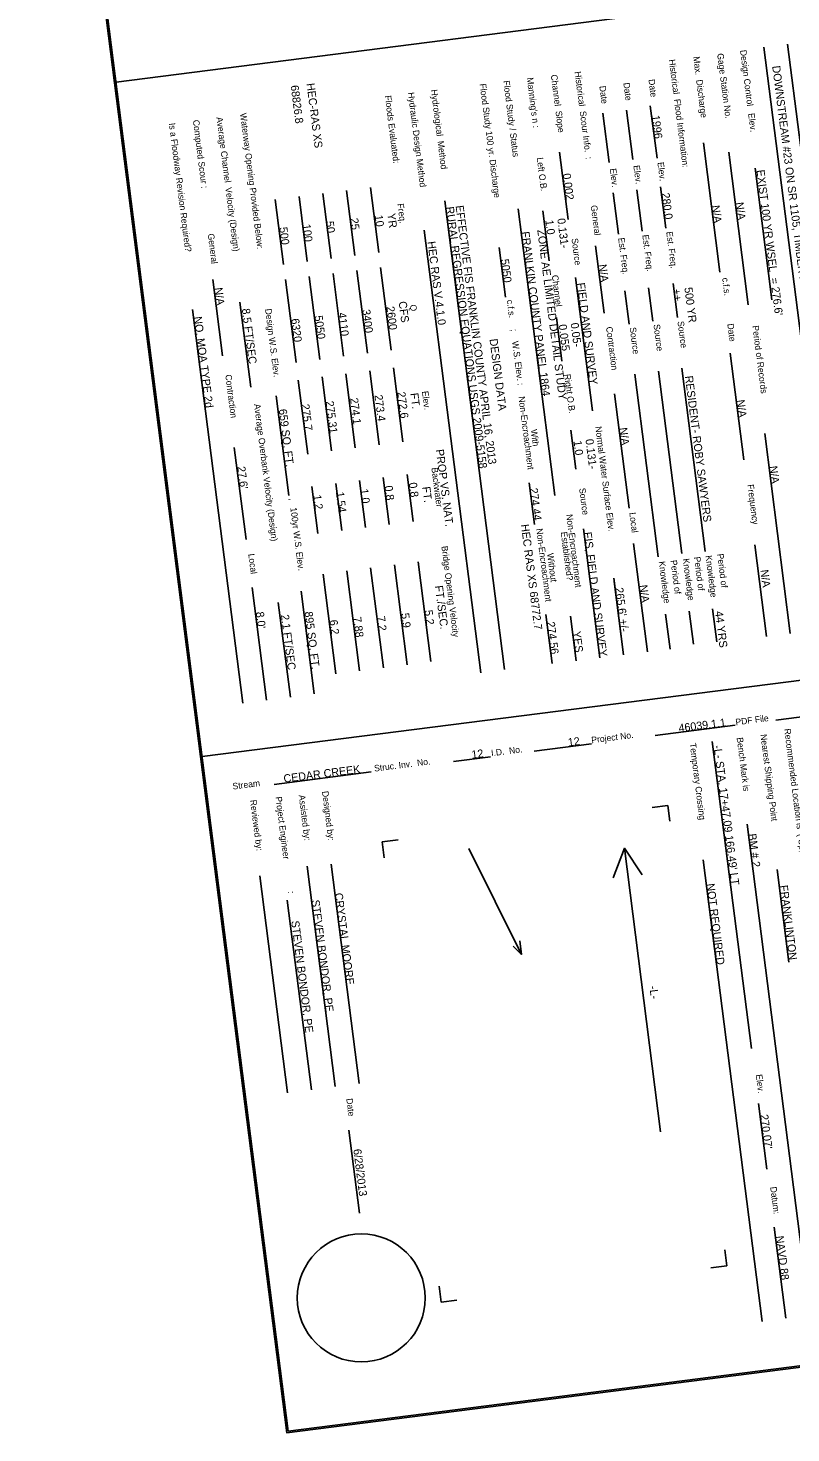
# Model space of a CAD drawing. Extents: x 2166991 to 2168413, y 842679 to 844296.
# Drawn here: x 2166991 to 2167468, y 842679 to 843557 of the extents above; entities that cross this region are included whole.
import ezdxf

# ---------------------------------------------------------------- set-up
doc = ezdxf.new("R2010")
doc.units = 0
for name, color, linetype in [('Old_Level_19', 7, 'Continuous'), ('Prop Plan Preparation Cover Label', 7, 'Continuous'), ('Prop Plan Preparation Sheet Bridge Report Limited Study CELL', 7, 'Continuous'), ('Sheet Plot Border Outside CELL', 7, 'Continuous')]:
    doc.layers.add(name, color=color, linetype=linetype)

msp = doc.modelspace()

# ---------------------------------------------------------------- linework, layer by layer
at = {"layer": 'Old_Level_19'}
for p, q in [((2167364.14, 843044.08), (2167357.17, 843025.57)), ((2167299.79, 842977.75), (2167294.54, 842982.82))]:
    msp.add_line(p, q, dxfattribs=at)
for points in [[(2167266.81, 843043.83), (2167299.79, 842977.75), (2167298.7, 842986.29)], [(2167386.79, 842866.75), (2167364.14, 843044.08), (2167375.24, 843027.53)]]:
    msp.add_lwpolyline(points, dxfattribs=at)
at = {"layer": 'Prop Plan Preparation Sheet Bridge Report Limited Study CELL'}
for p, q in [((2167046.37, 843522.95), (2167591.94, 843592.64)), ((2167497.56, 843182.31), (2167451.28, 843544.69)), ((2167512.44, 843184.21), (2167466.16, 843546.59)), ((2167380.33, 843508.19), (2167384.53, 843475.3)), ((2167350.63, 843503.57), (2167354.58, 843472.75)), ((2167365.51, 843505.47), (2167369.44, 843474.64)), ((2167423.86, 843404.17), (2167413.54, 843484.99)), ((2167328.93, 843437.01), (2167323.56, 843479.07)), ((2167441.6, 843383.67), (2167429.4, 843479.19)), ((2167456.32, 843386.86), (2167445.81, 843469.08)), ((2167195.7, 843414.6), (2167190.52, 843455.16)), ((2167210.58, 843416.5), (2167205.4, 843457.06)), ((2167371.93, 843455.61), (2167375.23, 843429.7)), ((2167386.8, 843457.51), (2167390.11, 843431.6)), ((2167151.06, 843408.9), (2167145.88, 843449.45)), ((2167165.94, 843410.8), (2167160.76, 843451.35)), ((2167180.82, 843412.7), (2167175.64, 843453.25)), ((2167289.26, 843155.7), (2167251.84, 843448.63)), ((2167357.05, 843453.71), (2167360.35, 843427.8)), ((2167320.71, 843264.62), (2167297.83, 843443.75)), ((2167317.12, 843411.12), (2167313.11, 843442.49)), ((2167274.38, 843153.8), (2167239.04, 843430.48)), ((2167289.77, 843388.48), (2167285.81, 843419.45)), ((2167351.53, 843378.49), (2167346.16, 843420.55)), ((2167173.75, 843349.64), (2167167.14, 843401.42)), ((2167188.63, 843351.54), (2167182.02, 843403.32)), ((2167203.51, 843353.44), (2167196.9, 843405.22)), ((2167218.39, 843355.34), (2167211.78, 843407.12)), ((2167113, 843351.76), (2167106.88, 843399.61)), ((2167158.87, 843347.74), (2167152.26, 843399.52)), ((2167344.2, 843317.53), (2167333.57, 843400.7)), ((2167367.07, 843371.56), (2167364.4, 843392.48)), ((2167381.95, 843373.46), (2167379.28, 843394.38)), ((2167397.25, 843375.73), (2167394.54, 843396.96)), ((2167130.6, 843332.3), (2167123.83, 843385.32)), ((2167125.59, 843134.8), (2167094.16, 843380.82)), ((2167325.11, 843348.56), (2167321.64, 843375.74)), ((2167438.86, 843286.78), (2167430.34, 843353.46)), ((2167195.95, 843294.27), (2167190.04, 843340.53)), ((2167210.83, 843296.17), (2167204.92, 843342.43)), ((2167225.71, 843298.07), (2167219.8, 843344.33)), ((2167370.65, 843340.3), (2167385.21, 843226.32)), ((2167385.53, 843342.2), (2167400.09, 843228.22)), ((2167400.04, 843344.06), (2167414.65, 843229.65)), ((2167166.19, 843290.47), (2167160.28, 843336.73)), ((2167181.07, 843292.37), (2167175.16, 843338.63)), ((2167154.38, 843264.5), (2167146.42, 843326.82)), ((2167367.1, 843256.58), (2167357.96, 843328.15)), ((2167333.75, 843280.92), (2167330.63, 843305.37)), ((2167467.83, 843178.32), (2167451.86, 843303.37)), ((2167127.64, 843237.11), (2167120.29, 843294.61)), ((2167172.54, 843240.74), (2167168.79, 843270.09)), ((2167187.42, 843242.64), (2167183.67, 843271.99)), ((2167202.3, 843244.54), (2167198.55, 843273.89)), ((2167217.18, 843246.44), (2167213.43, 843275.79)), ((2167232.06, 843248.34), (2167228.31, 843277.69)), ((2167307.92, 843246.36), (2167304.6, 843272.39)), ((2167348.8, 843163.12), (2167338.5, 843243.75)), ((2167378.56, 843166.92), (2167369.92, 843234.52)), ((2167452.95, 843176.42), (2167445.64, 843233.66)), ((2167198.62, 843155), (2167190.65, 843217.37)), ((2167213.49, 843156.91), (2167205.53, 843219.27)), ((2167228.37, 843158.81), (2167220.41, 843221.17)), ((2167243.25, 843160.71), (2167235.28, 843223.08)), ((2167183.73, 843153.11), (2167175.77, 843215.47)), ((2167363.68, 843165.02), (2167357.57, 843212.86)), ((2167363.68, 843165.02), (2167357.84, 843210.7)), ((2167140.47, 843136.7), (2167131.47, 843207.14)), ((2167170.22, 843140.5), (2167162, 843204.85)), ((2167155.34, 843138.6), (2167147.8, 843197.7)), ((2167404.62, 843192.35), (2167407.26, 843171.63)), ((2167419.28, 843193.81), (2167421.93, 843173.05)), ((2167319.02, 843159.5), (2167315.09, 843190.23)), ((2167333.91, 843161.3), (2167330.35, 843189.15)), ((2167392.66, 843168.61), (2167389.87, 843190.42)), ((2167100.22, 843101.38), (2167645.78, 843171.06)), ((2167458.71, 843124.09), (2167636.89, 843146.84)), ((2167383.33, 843114.5), (2167433.45, 843120.91)), ((2167307.67, 843104.86), (2167343.5, 843109.43)), ((2167419.09, 843110.89), (2167443.62, 842918.85)), ((2167257.33, 843098.33), (2167280.43, 843101.28)), ((2167145.22, 843084.01), (2167205.85, 843091.76)), ((2167381.44, 843069.57), (2167391.36, 843070.84)), ((2167391.36, 843070.84), (2167392.62, 843060.92)), ((2167440.83, 843059.14), (2167480.03, 842752.21)), ((2167212.81, 843048.04), (2167222.73, 843049.3)), ((2167214.07, 843038.12), (2167212.81, 843048.04)), ((2167165.79, 843032.93), (2167183.4, 842895.1)), ((2167180.77, 843034.04), (2167198.28, 842897)), ((2167413.43, 843036.88), (2167450.27, 842748.4)), ((2167136.32, 843026.86), (2167153.64, 842891.3)), ((2167459.57, 843030.75), (2167466.95, 842972.99)), ((2167153.39, 843011.65), (2167168.52, 842893.2)), ((2167448, 842884.62), (2167453.24, 842843.59)), ((2167191.96, 842867.86), (2167198.59, 842815.99)), ((2167457.86, 842807.36), (2167465.15, 842750.31)), ((2167426.83, 842793.1), (2167428.1, 842783.18)), ((2167428.1, 842783.18), (2167418.18, 842781.91)), ((2167249.55, 842760.37), (2167248.28, 842770.29)), ((2167259.47, 842761.64), (2167249.55, 842760.37))]:
    msp.add_line(p, q, dxfattribs=at)
msp.add_lwpolyline([(2166992.52, 843944.53), (2167154.06, 842679.8), (2168245.2, 842819.17), (2168083.66, 844083.9)], close=True, dxfattribs=at)
msp.add_circle((2167199.68, 842763.05), 40, dxfattribs=at)
at = {"layer": 'Sheet Plot Border Outside CELL'}
msp.add_lwpolyline([(2168246.32, 842818.31), (2168084.52, 844085.01), (2166991.4, 843945.39), (2167153.2, 842678.68)], close=True, dxfattribs=at)

# ---------------------------------------------------------------- texts
at = {"layer": 'Old_Level_19'}
msp.add_text('-L-', height=5, rotation=277.27898, dxfattribs=at).set_placement((2167379.73, 842957.73))
at = {"layer": 'Prop Plan Preparation Cover Label'}
for s, rotation, p in [("DOWNSTREAM #23 ON SR 1105, TIMBER FLOOR ON I-BEAMS, 1@35.5', 2@35', 1@35.5", 277.27898, (2167456.49, 843532.9)), ('68826.8', 277.27898, (2167155.52, 843520.72)), ('HEC-RAS XS', 277.27898, (2167165.44, 843521.99)), ('1996', 277.27898, (2167381.17, 843501.98)), ('0.002', 277.27898, (2167325.59, 843465.57)), ("EXIST 100 YR WSEL  = 276.6'", 277.27898, (2167446.69, 843467.83)), ('EFFECTIVE FIS FRANKLIN COUNTY APRIL 16, 2013', 277.27898, (2167258.62, 843445.58)), ('280.0', 277.27898, (2167387.37, 843453.45)), ('N/A', 277.27898, (2167418.68, 843445.67)), ('N/A', 277.27898, (2167433.61, 843447.58)), ('25', 277.27898, (2167192.76, 843437.7)), ('10', 277.27898, (2167208.06, 843439.65)), ('YR', 277.27898, (2167215.97, 843440.66)), ('RURAL REGRESSION EQUATIONS USGS 2009-5158', 277.27898, (2167252.54, 843444.8)), ('1.0', 277.27898, (2167314.71, 843436.55)), ('0.131-', 277.27898, (2167322.15, 843437.51)), ('500', 277.27898, (2167148.44, 843432.04)), ('100', 277.27898, (2167162.94, 843433.89)), ('50', 277.27898, (2167177.45, 843435.74)), ('FRANLKIN COUNTY PANEL 1864', 277.27898, (2167299.73, 843429.26)), ('ZONE AE LIMITED DETAIL STUDY', 277.27898, (2167309.65, 843430.53)), ('HEC RAS V.4.1.0', 277.27898, (2167241.01, 843423.14)), ('5050', 277.27898, (2167286.9, 843412.08)), ('N/A', 277.27898, (2167347.93, 843408.76)), ('N/A', 277.27898, (2167107.89, 843394.24)), ('FIELD AND SURVEY', 277.27898, (2167334.44, 843397.26)), ('++', 277.27898, (2167394.17, 843393.46)), ('500 YR ', 277.27898, (2167401.61, 843394.41)), ('CFS', 277.27898, (2167223, 843385.63)), ('NO, MOA TYPE 2d', 277.27898, (2167094.99, 843376.15)), ('8.5 FT/SEC', 277.27898, (2167125.03, 843381.14)), ('6320', 277.27898, (2167155.82, 843374.91)), ('5050', 277.27898, (2167170.48, 843376.79)), ('4110', 277.27898, (2167185.15, 843378.66)), ('3400', 277.27898, (2167200.25, 843380.59)), ('2600', 277.27898, (2167215.36, 843382.52)), ('0.055', 277.27898, (2167323.05, 843371.24)), ('0.05-', 277.27898, (2167330.49, 843372.19)), ('RESIDENT- ROBY SAWYERS', 277.27898, (2167401.98, 843339.1)), ('275.31', 277.27898, (2167177.42, 843323.35)), ('274.1', 277.27898, (2167192.66, 843325.3)), ('273.4', 277.27898, (2167207.9, 843327.24)), ('272.6', 277.27898, (2167222.19, 843329.07)), ('FT.', 277.27898, (2167230.31, 843328.37)), ('N/A', 277.27898, (2167434.21, 843324.11)), ('659 SQ. FT.', 277.27898, (2167148.07, 843318.32)), ('275.7', 277.27898, (2167162.19, 843321.41)), ('N/A', 277.27898, (2167360.96, 843306.75)), ('1.0', 277.27898, (2167332.33, 843298.63)), ('0.131-', 277.27898, (2167339.77, 843299.58)), ('PROP VS. NAT.', 277.27898, (2167246.24, 843293.15)), ("27.6'", 277.27898, (2167122.16, 843282.51)), ('N/A', 277.27898, (2167454.75, 843282.77)), ('0.8', 277.27898, (2167214.22, 843270.45)), ('0.8', 277.27898, (2167229.43, 843272.4)), ('FT.', 277.27898, (2167237.79, 843269.85)), ('1.2', 277.27898, (2167169.63, 843264.76)), ('1.54', 277.27898, (2167183.8, 843266.57)), ('1.0', 277.27898, (2167199.01, 843268.51)), ('274.44', 277.27898, (2167304.93, 843268.99)), ('HEC RAS XS 68772.7', 277.27898, (2167299.49, 843246.32)), ('FIS, FIELD AND SURVEY', 277.27898, (2167338.62, 843241.45)), ('N/A', 277.27898, (2167449.14, 843217.9)), ('FT./SEC.', 277.27898, (2167245.68, 843208.03)), ('N/A', 277.27898, (2167373.52, 843208.43)), ("265.6' +/-", 277.27898, (2167358.39, 843206.75)), ("8.0'", 277.27898, (2167133.77, 843191.61)), ('895 SQ. FT.', 277.27898, (2167164.23, 843191.76)), ('5.9', 277.27898, (2167224.54, 843190.81)), ('5.2', 277.27898, (2167239.21, 843192.68)), ('44 YRS', 277.27898, (2167420.76, 843192.04)), ('2.1 FT/SEC', 277.27898, (2167149.46, 843189.87)), ('6.2', 277.27898, (2167179.81, 843186.59)), ('7.88', 277.27898, (2167194.58, 843188.47)), ('7.2', 277.27898, (2167209.46, 843188.89)), ('274.56', 277.27898, (2167315.61, 843185.38)), ('YES', 277.27898, (2167331.78, 843179.42)), ('46039.1.1', 7.27898, (2167398.31, 843116.61)), ('12', 7.27898, (2167329.16, 843107.77)), ('12', 7.27898, (2167268.91, 843100.08)), ("-L- STA. 17+47.09 166.49' LT", 277.27898, (2167419.91, 843108.12)), ('CEDAR CREEK', 7.27898, (2167151.4, 843085.07)), ('BM # 2 ', 277.27898, (2167441.53, 843052.93)), ('CRYSTAL MOORE', 277.27898, (2167183, 843015.87)), ('NOT REQUIRED', 277.27898, (2167415.45, 843021.77)), ('FRANKLINTON', 277.27898, (2167461.25, 843020.77)), ('STEVEN BONDOR, PE', 277.27898, (2167168.56, 843011.53)), ('STEVEN BONDOR, PE', 277.27898, (2167155.86, 842998.51)), ("270.07'", 277.27898, (2167449.03, 842877.45)), ('6/28/2013', 277.27898, (2167194.66, 842855.84)), ('NAVD 88', 277.27898, (2167458.72, 842801.57))]:
    msp.add_text(s, height=5, rotation=rotation, dxfattribs=at).set_placement(p)
at = {"layer": 'Prop Plan Preparation Sheet Bridge Report Limited Study CELL'}
for s, height, rotation, p in [('Design Control   Elev.', 4, 277.27898, (2167436.41, 843542.79)), ('Historical  Flood Information:', 4, 277.27898, (2167391.94, 843536.9)), ('Max.  Discharge', 4, 277.27898, (2167407.12, 843538.7)), ('Gage Station No.', 4, 277.27898, (2167422.11, 843540.68)), ("Manning's n :", 4, 277.27898, (2167303.12, 843525.54)), ('Channel  Slope', 4, 277.27898, (2167318.15, 843527.43)), ('Historical  Scour Info.  :', 4, 277.27898, (2167333.03, 843529.37)), ('Date', 4, 277.27898, (2167379.19, 843524.51)), ('Hydraulic Design Method', 4, 277.27898, (2167228.8, 843516.32)), ('Hydrological  Method', 4, 277.27898, (2167243.17, 843518.06)), ('Flood Study 100 yr. Discharge', 4, 277.27898, (2167273.67, 843521.79)), ('Flood Study / Status', 4, 277.27898, (2167288.39, 843523.68)), ('Date', 4, 277.27898, (2167348.47, 843520.36)), ('Date', 4, 277.27898, (2167363.46, 843522.37)), ('Floods Evaluated:', 4, 277.27898, (2167214.34, 843514.35)), ('Computed Scour :', 4, 277.27898, (2167094.39, 843499.08)), ('Average Channel  Velocity (Design)', 4, 277.27898, (2167109.08, 843500.87)), ('Waterway Opening Provided Below:', 4, 277.27898, (2167123.87, 843503.32)), ('Is a Floodway Revision Required?', 4, 277.27898, (2167079.4, 843497.15)), ('Left O.B.', 4, 277.27898, (2167309.33, 843475.59)), ('Elev.', 4, 277.27898, (2167384.76, 843472.66)), ('Elev.', 4, 277.27898, (2167355.05, 843468.76)), ('Elev.', 4, 277.27898, (2167369.74, 843470.74)), ('Freq.', 4, 277.27898, (2167222.21, 843446.83)), ('General', 4, 277.27898, (2167343.1, 843445.76)), ('General', 4, 277.27898, (2167103.67, 843428.02)), ('Est. Freq.', 4, 277.27898, (2167390.29, 843429.3)), ('Source', 4, 277.27898, (2167331.11, 843425.08)), ('Est. Freq.', 4, 277.27898, (2167360.25, 843425.43)), ('Est. Freq.', 4, 277.27898, (2167375.34, 843427.36)), ('Channel', 4, 277.27898, (2167318.75, 843402.14)), ('c.f.s.', 4, 277.27898, (2167425.23, 843400.43)), ('Q', 4, 277.27898, (2167230.07, 843383.65)), ('c.f.s.', 4, 277.27898, (2167290.59, 843386.62)), ('Design W.S. Elev.', 4, 277.27898, (2167139.52, 843381.08)), (';', 4, 277.27898, (2167293.1, 843368.33)), ('Contraction', 4, 277.27898, (2167352.67, 843369.81)), ('Source', 4, 277.27898, (2167367.43, 843369.47)), ('Source', 4, 277.27898, (2167382.33, 843371.37)), ('Source', 4, 277.27898, (2167397.34, 843373.33)), ('Date', 4, 277.27898, (2167428.44, 843371.79)), ('Period of Records', 4, 277.27898, (2167444.11, 843370.57)), ('DESIGN DATA', 5, 277.27898, (2167279.82, 843362.25)), ('W.S. Elev. :', 4, 277.27898, (2167293.9, 843360.84)), ('Contraction', 4, 277.27898, (2167114.65, 843339.93)), ('Right O.B.', 4, 277.27898, (2167326.49, 843340.21)), ('Elev.', 4, 277.27898, (2167237.59, 843329.62)), ('Non-Encroachment', 4, 277.27898, (2167297.9, 843326.27)), ('Average Overbank Velocity (Design)', 4, 277.27898, (2167132.62, 843321.58)), ('With', 4, 277.27898, (2167305.57, 843305.69)), ('Normal Water Surface Elev.', 4, 277.27898, (2167345.9, 843307.54)), ('Backwater', 4, 277.27898, (2167243.49, 843281.81)), ('Frequency', 4, 277.27898, (2167441.05, 843271.27)), (',   100yr W.S. Elev.', 4, 277.27898, (2167154.55, 843262.71)), ('Source', 4, 277.27898, (2167335.85, 843268.99)), ('Non-Encroachment', 4, 277.27898, (2167327.76, 843252.61)), ('Local', 4, 277.27898, (2167367.23, 843253.75)), ('Non-Encroachment', 4, 277.27898, (2167309.02, 843243.72)), ('Established?', 4, 277.27898, (2167324.33, 843241.63)), ('Local', 4, 277.27898, (2167129.03, 843227.97)), ('Bridge Opening Velocity', 4, 277.27898, (2167249.75, 843232.79)), ('Without', 4, 277.27898, (2167315.83, 843228.28)), ('Period of', 4, 277.27898, (2167407.62, 843226.04)), ('Knowledge', 4, 277.27898, (2167414.78, 843226.87)), ('Period of', 4, 277.27898, (2167422.08, 843227.93)), ('Knowledge', 4, 277.27898, (2167385.58, 843223.21)), ('Period of', 4, 277.27898, (2167392.96, 843223.97)), ('Knowledge', 4, 277.27898, (2167400.61, 843224.93)), ('PDF File', 4, 7.27898, (2167433.84, 843120.91)), ('Project No.', 4, 7.27898, (2167343.74, 843109.67)), ('Bench Mark is', 4, 277.27898, (2167434.28, 843113.13)), ('Nearest Shipping Point', 4, 277.27898, (2167449.14, 843115.12)), ('Recommended Location is  ( Up, At, Down)  Stream from Existing Crossing.', 4, 277.27898, (2167463.99, 843118.64)), ('I.D.  No.', 4, 7.27898, (2167281.08, 843101.56)), ('Temporary Crossing', 4, 277.27898, (2167404.91, 843109.62)), ('Struc. Inv.  No.', 4, 7.27898, (2167207.94, 843092)), ('Stream', 4, 7.27898, (2167119.46, 843080.77)), ('Assisted by:', 4, 277.27898, (2167160.52, 843077.23)), ('Designed by:', 4, 277.27898, (2167175.11, 843079.61)), ('Reviewed by:', 4, 277.27898, (2167130.13, 843074.11)), ('Project Engineer', 4, 277.27898, (2167146.01, 843076.14)), (':', 4, 277.27898, (2167153.79, 843017.02)), ('Elev.', 4, 277.27898, (2167446.29, 842902.57)), ('Date', 4, 277.27898, (2167190.27, 842887.54)), ('Datum:', 4, 277.27898, (2167455.27, 842832.32))]:
    msp.add_text(s, height=height, rotation=rotation, dxfattribs=at).set_placement(p)

doc.saveas('drawing.dxf')
